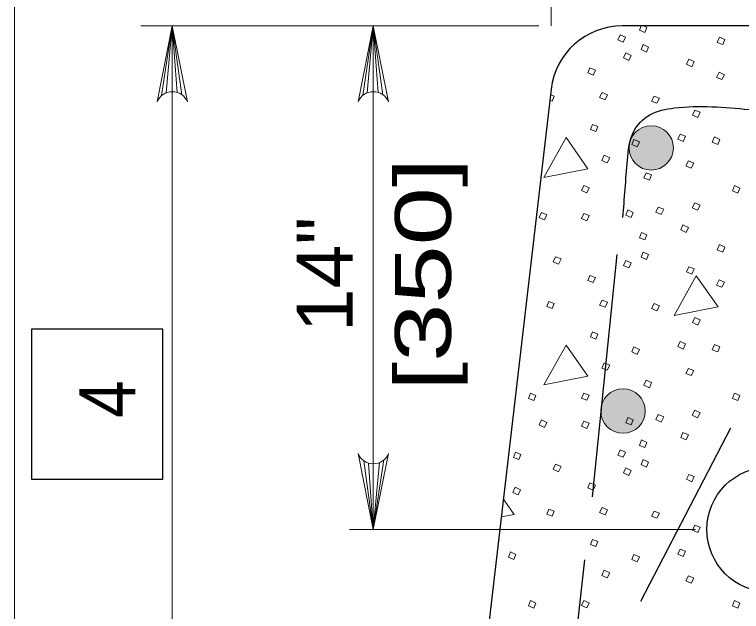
# Model space of a CAD drawing. Extents: x 1083.1 to 1123, y 697.4 to 741.4.
# Drawn here: x 1088.686 to 1090.714, y 715.414 to 717.078 of the extents above; entities that cross this region are included whole.
import ezdxf
from ezdxf.enums import TextEntityAlignment as Align

# ---------------------------------------------------------------- set-up
doc = ezdxf.new("R2010")
doc.units = 0
doc.header["$LTSCALE"] = 0.062
doc.layers.add('1', color=7, linetype='Continuous', lineweight=13)

msp = doc.modelspace()

# ---------------------------------------------------------------- hatches: boundary and pattern name
at = {"layer": '1'}
h = msp.add_hatch(color=256, dxfattribs=at)
edge = h.paths.add_edge_path()
edge.add_ellipse((1090.46199, 716.70652), major_axis=(0.06191, 0), ratio=0.9998948, start_angle=0, end_angle=360)
h = msp.add_hatch(color=256, dxfattribs=at)
edge = h.paths.add_edge_path()
edge.add_ellipse((1090.38326, 715.97273), major_axis=(0.06191, 0), ratio=0.9998948, start_angle=0, end_angle=360)

# ---------------------------------------------------------------- linework, layer by layer
for p, q in [((1088.68575, 713.66983), (1088.68575, 717.83325)), ((1090.18242, 717.04658), (1090.18242, 717.83325)), ((1090.14817, 717.04658), (1089.03775, 717.04658)), ((1089.09608, 716.85233), (1089.12583, 717.04658)), ((1089.10858, 716.85975), (1089.12583, 717.04658)), ((1089.12583, 713.57925), (1089.12583, 717.04658)), ((1089.12583, 716.86308), (1089.12583, 717.04658)), ((1089.13933, 716.86108), (1089.12583, 717.04658)), ((1089.15267, 716.85458), (1089.12583, 717.04658)), ((1089.657, 716.85233), (1089.68667, 717.04658)), ((1089.66942, 716.85975), (1089.68667, 717.04658)), ((1089.68667, 717.04658), (1089.68667, 715.64233)), ((1089.68667, 716.86308), (1089.68667, 717.04658)), ((1089.70025, 716.86108), (1089.68667, 717.04658)), ((1089.7135, 716.85458), (1089.68667, 717.04658)), ((1089.71633, 715.83658), (1089.68667, 715.64233)), ((1089.65983, 715.83433), (1089.68667, 715.64233)), ((1089.67308, 715.82783), (1089.68667, 715.64233)), ((1089.70392, 715.82925), (1089.68667, 715.64233)), ((1089.68667, 715.82583), (1089.68667, 715.64233)), ((1090.58525, 715.64233), (1089.62017, 715.64233))]:
    msp.add_line(p, q, dxfattribs=at)
at = {"layer": '1', "lineweight": 25}
for p, q in [((1091.22108, 717.04658), (1090.38058, 717.04658)), ((1090.36608, 716.40933), (1090.29692, 715.73367)), ((1090.68325, 715.92508), (1090.43217, 715.44192)), ((1090.27608, 715.55825), (1090.18383, 714.73175))]:
    msp.add_line(p, q, dxfattribs=at)
at = {"layer": '1'}
for points in [[(1089.08342, 716.83458), (1089.12583, 717.04658), (1089.16817, 716.83458)], [(1089.64425, 716.83458), (1089.68667, 717.04658), (1089.72908, 716.83458)], [(1090.44075, 717.04658), (1090.44975, 717.04242), (1090.44375, 717.02842), (1090.42883, 717.03442), (1090.43367, 717.04658)], [(1090.18067, 716.85517), (1090.19133, 716.85083), (1090.18533, 716.83683), (1090.17883, 716.8395)], [(1089.72908, 715.85442), (1089.68667, 715.64233), (1089.64425, 715.85442)], [(1090.0435, 715.6775), (1090.07958, 715.68458), (1090.04933, 715.72775)]]:
    msp.add_lwpolyline(points, dxfattribs=at)
for points in [[(1090.37492, 717.02142), (1090.38992, 717.01542), (1090.38392, 717.0015), (1090.36892, 717.0075)], [(1090.65233, 717.01542), (1090.66725, 717.0085), (1090.66133, 716.9945), (1090.64633, 717.0005)], [(1090.43975, 716.9945), (1090.45475, 716.9875), (1090.44875, 716.97358), (1090.43383, 716.9805)], [(1090.39092, 716.97158), (1090.40583, 716.96458), (1090.39992, 716.95058), (1090.38492, 716.95758)], [(1090.5665, 716.95358), (1090.5815, 716.94758), (1090.5755, 716.93267), (1090.5605, 716.93967)], [(1090.29108, 716.92967), (1090.30608, 716.92367), (1090.30008, 716.90967), (1090.28517, 716.91567)], [(1090.65133, 716.91767), (1090.66625, 716.91067), (1090.65933, 716.89675), (1090.64433, 716.90275)], [(1090.325, 716.86083), (1090.34, 716.85483), (1090.333, 716.84083), (1090.31808, 716.84683)], [(1090.46975, 716.85083), (1090.48467, 716.84483), (1090.47767, 716.83092), (1090.46275, 716.83683)], [(1090.5835, 716.81192), (1090.59842, 716.80592), (1090.59242, 716.791), (1090.5775, 716.798)], [(1090.29808, 716.772), (1090.31308, 716.766), (1090.30708, 716.75208), (1090.29208, 716.75808)], [(1090.22425, 716.73508), (1090.16242, 716.62433), (1090.28517, 716.64833)], [(1090.41383, 716.73008), (1090.42883, 716.72317), (1090.42283, 716.70917), (1090.40783, 716.71617)], [(1090.54258, 716.74508), (1090.5575, 716.73908), (1090.5515, 716.72417), (1090.53658, 716.73108)], [(1090.63833, 716.73708), (1090.65333, 716.73008), (1090.64733, 716.71617), (1090.63233, 716.72217)], [(1090.331, 716.68625), (1090.346, 716.67925), (1090.339, 716.66525), (1090.32408, 716.67125)], [(1090.5655, 716.67025), (1090.5805, 716.66425), (1090.5735, 716.65033), (1090.5585, 716.65625)], [(1090.44775, 716.63733), (1090.46275, 716.63133), (1090.45675, 716.61642), (1090.44175, 716.62333)], [(1090.27417, 716.60142), (1090.28908, 716.59542), (1090.28217, 716.5815), (1090.26717, 716.58742)], [(1090.69425, 716.60142), (1090.70917, 716.59442), (1090.70317, 716.5805), (1090.68825, 716.58642)], [(1090.5835, 716.5535), (1090.59842, 716.54658), (1090.59142, 716.53258), (1090.5765, 716.53958)], [(1090.15542, 716.52658), (1090.17042, 716.51958), (1090.16442, 716.50567), (1090.14942, 716.51267)], [(1090.39692, 716.53358), (1090.41183, 716.52658), (1090.40583, 716.51267), (1090.39092, 716.51858)], [(1090.48167, 716.54158), (1090.49667, 716.53558), (1090.48967, 716.52058), (1090.47467, 716.52758)], [(1090.27417, 716.52358), (1090.28908, 716.51758), (1090.28217, 716.50267), (1090.26717, 716.50958)], [(1090.5505, 716.49167), (1090.5655, 716.48467), (1090.5595, 716.47075), (1090.54458, 716.47767)], [(1090.43483, 716.47075), (1090.44975, 716.46375), (1090.44375, 716.44975), (1090.42883, 716.45575)], [(1090.65233, 716.43683), (1090.66725, 716.42983), (1090.66133, 716.41583), (1090.64633, 716.42183)], [(1090.43975, 716.41583), (1090.45475, 716.40883), (1090.44875, 716.39492), (1090.43383, 716.40192)], [(1090.19533, 716.40292), (1090.21033, 716.39692), (1090.20333, 716.38192), (1090.18833, 716.38892)], [(1090.39092, 716.39292), (1090.40583, 716.38592), (1090.39992, 716.37192), (1090.38492, 716.37892)], [(1090.5665, 716.37492), (1090.5815, 716.369), (1090.5755, 716.354), (1090.5605, 716.361)], [(1090.29108, 716.351), (1090.30608, 716.345), (1090.30008, 716.331), (1090.28517, 716.337)], [(1090.58742, 716.35), (1090.52558, 716.23925), (1090.64833, 716.26317)], [(1090.65133, 716.339), (1090.66625, 716.332), (1090.65933, 716.31808), (1090.64433, 716.32408)], [(1090.325, 716.28217), (1090.34, 716.27617), (1090.333, 716.26217), (1090.31808, 716.26817)], [(1090.17633, 716.27817), (1090.19133, 716.27217), (1090.18533, 716.25825), (1090.17042, 716.26417)], [(1090.46975, 716.27217), (1090.48467, 716.26617), (1090.47767, 716.25225), (1090.46275, 716.25825)], [(1090.5835, 716.23325), (1090.59842, 716.22725), (1090.59242, 716.21233), (1090.5775, 716.21933)], [(1090.29808, 716.19333), (1090.31308, 716.18733), (1090.30708, 716.17342), (1090.29208, 716.17942)], [(1090.54258, 716.16642), (1090.5575, 716.16042), (1090.5515, 716.1455), (1090.53658, 716.1525)], [(1090.22425, 716.15642), (1090.16242, 716.04575), (1090.28517, 716.06967)], [(1090.41383, 716.1515), (1090.42883, 716.1445), (1090.42283, 716.1305), (1090.40783, 716.1375)], [(1090.63833, 716.15842), (1090.65333, 716.1515), (1090.64733, 716.1375), (1090.63233, 716.1435)], [(1090.331, 716.10758), (1090.346, 716.10058), (1090.339, 716.08658), (1090.32408, 716.09258)], [(1090.5655, 716.09158), (1090.5805, 716.08558), (1090.5735, 716.07167), (1090.5585, 716.07767)], [(1090.44775, 716.05867), (1090.46275, 716.05267), (1090.45675, 716.03775), (1090.44175, 716.04475)], [(1090.1255, 716.02275), (1090.14042, 716.01575), (1090.1345, 716.00183), (1090.1195, 716.00783)], [(1090.27417, 716.02275), (1090.28908, 716.01675), (1090.28217, 716.00283), (1090.26717, 716.00883)], [(1090.69425, 716.02275), (1090.70917, 716.01575), (1090.70317, 716.00183), (1090.68825, 716.00783)], [(1090.48167, 715.96292), (1090.49667, 715.95692), (1090.48967, 715.94192), (1090.47467, 715.94892)], [(1090.5835, 715.97492), (1090.59842, 715.96792), (1090.59142, 715.95392), (1090.5765, 715.96092)], [(1090.15542, 715.94792), (1090.17042, 715.94092), (1090.16442, 715.927), (1090.14942, 715.934)], [(1090.27417, 715.94492), (1090.28908, 715.939), (1090.28217, 715.924), (1090.26717, 715.931)], [(1090.39692, 715.95492), (1090.41183, 715.94792), (1090.40583, 715.934), (1090.39092, 715.93992)], [(1090.5505, 715.913), (1090.5655, 715.906), (1090.5595, 715.89208), (1090.54458, 715.89908)], [(1090.43483, 715.89208), (1090.44975, 715.88508), (1090.44375, 715.87108), (1090.42883, 715.87708)], [(1090.08358, 715.85817), (1090.09858, 715.85117), (1090.09258, 715.83717), (1090.07758, 715.84317)], [(1090.37492, 715.86417), (1090.38992, 715.85817), (1090.38392, 715.84417), (1090.36892, 715.85017)], [(1090.43975, 715.83717), (1090.45475, 715.83025), (1090.44875, 715.81625), (1090.43383, 715.82325)], [(1090.19533, 715.82425), (1090.21033, 715.81825), (1090.20333, 715.80325), (1090.18833, 715.81025)], [(1090.39092, 715.81425), (1090.40583, 715.80725), (1090.39992, 715.79333), (1090.38492, 715.80025)], [(1090.5665, 715.79625), (1090.5815, 715.79033), (1090.5755, 715.77533), (1090.5605, 715.78233)], [(1090.08258, 715.76042), (1090.09758, 715.75342), (1090.09058, 715.73942), (1090.07558, 715.74542)], [(1090.29108, 715.77233), (1090.30608, 715.76633), (1090.30008, 715.75242), (1090.28517, 715.75842)], [(1090.17633, 715.6995), (1090.19133, 715.6935), (1090.18533, 715.67958), (1090.17042, 715.68558)], [(1090.325, 715.7035), (1090.34, 715.6975), (1090.333, 715.68358), (1090.31808, 715.6895)], [(1090.46975, 715.6935), (1090.48467, 715.68758), (1090.47767, 715.67358), (1090.46275, 715.67958)], [(1090.5835, 715.65467), (1090.59842, 715.64867), (1090.59242, 715.63367), (1090.5775, 715.64067)], [(1090.29808, 715.61475), (1090.31308, 715.60875), (1090.30708, 715.59475), (1090.29208, 715.60075)], [(1090.06958, 715.57983), (1090.08458, 715.57283), (1090.07858, 715.55883), (1090.06358, 715.56483)], [(1090.41383, 715.57283), (1090.42883, 715.56583), (1090.42283, 715.55183), (1090.40783, 715.55883)], [(1090.54258, 715.58775), (1090.5575, 715.58183), (1090.5515, 715.56683), (1090.53658, 715.57383)], [(1090.331, 715.52892), (1090.346, 715.52192), (1090.339, 715.508), (1090.32408, 715.51392)], [(1090.5655, 715.51292), (1090.5805, 715.507), (1090.5735, 715.493), (1090.5585, 715.499)], [(1090.1255, 715.44408), (1090.14042, 715.43717), (1090.1345, 715.42317), (1090.1195, 715.42917)], [(1090.27417, 715.44408), (1090.28908, 715.43817), (1090.28217, 715.42417), (1090.26717, 715.43017)], [(1090.69425, 715.44408), (1090.70917, 715.43717), (1090.70317, 715.42317), (1090.68825, 715.42917)]]:
    msp.add_lwpolyline(points, close=True, dxfattribs=at)
at = {"layer": '1', "lineweight": 25}
msp.add_lwpolyline([(1090.18242, 716.87008), (1089.96042, 714.96533), (1089.26875, 713.89792), (1089.26875, 713.35117), (1088.68575, 713.35117)], dxfattribs=at)
msp.add_lwpolyline([(1088.73317, 715.7825), (1089.09958, 715.7825), (1089.09958, 716.20092), (1088.73317, 716.20092)], close=True, dxfattribs=at)
at = {"layer": '1'}
for centre, start, end in [((1089.12584, 716.81743), 22.08782, 157.91395), ((1089.68671, 716.81743), 22.08782, 157.91395), ((1089.68661, 715.87151), 202.08782, 337.91395)]:
    msp.add_arc(centre, 0.04576, start, end, dxfattribs=at)
at = {"layer": '1', "lineweight": 25}
msp.add_ellipse((1090.38066, 716.84704), major_axis=(0.19956, 0), ratio=0.999895, start_param=1.5707963, end_param=3.0255955, dxfattribs=at)
at = {"layer": '1'}
for centre in [(1090.46199, 716.70652), (1090.38326, 715.97273)]:
    msp.add_ellipse(centre, major_axis=(0.06191, 0), ratio=0.999895, dxfattribs=at)
at = {"layer": '1', "lineweight": 25}
msp.add_ellipse((1090.7915, 715.64235), major_axis=(0.17433, 0), ratio=0.999895, dxfattribs=at)
msp.add_spline([(1090.383, 716.51242), (1090.39558, 716.67233), (1090.41242, 716.751), (1090.45775, 716.79867), (1090.52658, 716.81783), (1090.73533, 716.81358)], degree=3, dxfattribs=at)

# ---------------------------------------------------------------- texts
at = {"layer": '1'}
for s, width, p in [('[350]', 1.4, (1089.90317, 716.35358)), ('14"', 1.05, (1089.62917, 716.35358))]:
    msp.add_text(s, height=0.156, rotation=90, dxfattribs=dict(at, width=width)).set_placement(p, align=Align.CENTER)
at = {"layer": '1', "width": 0.9}
msp.add_text('4', height=0.156, rotation=90, dxfattribs=at).set_placement((1089.0225, 715.95375))

doc.saveas('drawing.dxf')
